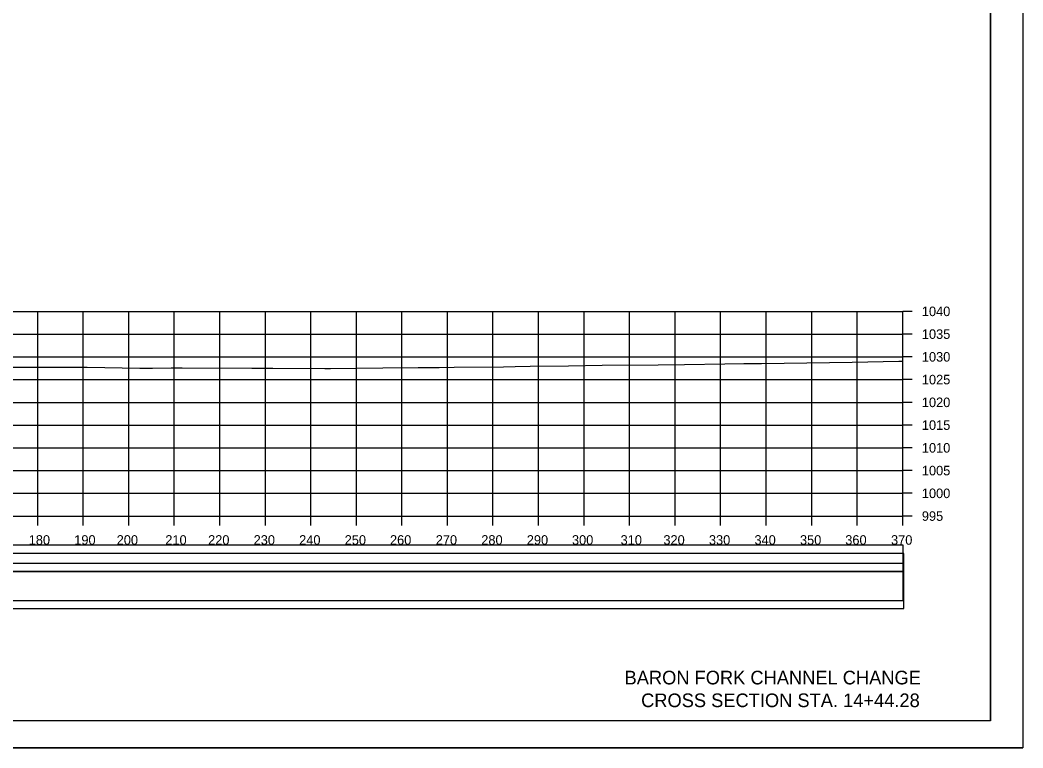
# Model space of a CAD drawing. Extents: x 1370565 to 1374448, y 301010 to 304637.
# Drawn here: x 1374227.6 to 1374447.9, y 302693 to 302853 of the extents above; entities that cross this region are included whole.
import ezdxf

# ---------------------------------------------------------------- set-up
doc = ezdxf.new("R2010")
doc.units = 0
for name, color, linetype in [('Default', 7, 'Continuous'), ('R_Axis', 7, 'Continuous'), ('R_Axis Annot', 7, 'Continuous'), ('R_Border', 7, 'Continuous'), ('R_Draft', 7, 'Continuous'), ('R_Drive', 7, 'Continuous'), ('R_Exist Surface', 7, 'Continuous'), ('R_Grid', 7, 'Continuous'), ('R_No Plot', 7, 'Continuous')]:
    doc.layers.add(name, color=color, linetype=linetype)

msp = doc.modelspace()

# ---------------------------------------------------------------- linework, layer by layer
at = {"layer": 'Default'}
for points in [[(1373981.44, 302733.61), (1374421.61, 302733.61), (1374421.61, 302737.6), (1373981.44, 302737.6)], [(1373981.44, 302725.39), (1374421.61, 302725.39), (1374421.61, 302733.53), (1373981.44, 302733.53)]]:
    msp.add_lwpolyline(points, close=True, dxfattribs=at)
at = {"layer": 'R_Axis'}
for p, q in [((1374421.52, 302743.98), (1374421.52, 302788.98)), ((1374423.62, 302788.98), (1374421.52, 302788.98)), ((1374423.62, 302783.98), (1374421.52, 302783.98)), ((1374423.62, 302778.98), (1374421.52, 302778.98)), ((1374423.62, 302773.98), (1374421.52, 302773.98)), ((1374423.62, 302768.98), (1374421.52, 302768.98)), ((1374423.62, 302763.98), (1374421.52, 302763.98)), ((1374423.62, 302758.98), (1374421.52, 302758.98)), ((1374423.62, 302753.98), (1374421.52, 302753.98)), ((1374423.62, 302748.98), (1374421.52, 302748.98)), ((1373981.52, 302743.98), (1374421.52, 302743.98)), ((1374231.52, 302741.88), (1374231.52, 302743.98)), ((1374241.52, 302741.88), (1374241.52, 302743.98)), ((1374251.52, 302741.88), (1374251.52, 302743.98)), ((1374261.52, 302741.88), (1374261.52, 302743.98)), ((1374271.52, 302741.88), (1374271.52, 302743.98)), ((1374281.52, 302741.88), (1374281.52, 302743.98)), ((1374291.52, 302741.88), (1374291.52, 302743.98)), ((1374301.52, 302741.88), (1374301.52, 302743.98)), ((1374311.52, 302741.88), (1374311.52, 302743.98)), ((1374321.52, 302741.88), (1374321.52, 302743.98)), ((1374331.52, 302741.88), (1374331.52, 302743.98)), ((1374341.52, 302741.88), (1374341.52, 302743.98)), ((1374351.52, 302741.88), (1374351.52, 302743.98)), ((1374361.52, 302741.88), (1374361.52, 302743.98)), ((1374371.52, 302741.88), (1374371.52, 302743.98)), ((1374381.52, 302741.88), (1374381.52, 302743.98)), ((1374391.52, 302741.88), (1374391.52, 302743.98)), ((1374401.52, 302741.88), (1374401.52, 302743.98)), ((1374411.52, 302741.88), (1374411.52, 302743.98)), ((1374421.52, 302741.88), (1374421.52, 302743.98)), ((1374423.62, 302743.98), (1374421.52, 302743.98))]:
    msp.add_line(p, q, dxfattribs=at)
at = {"layer": 'R_Border'}
for q in [(1374440.79, 303007.17), (1373966.52, 302698.98)]:
    msp.add_line((1374440.79, 302698.98), q, dxfattribs=at)
at = {"layer": 'R_Drive'}
for points in [[(1373981.52, 302731.78), (1374421.73, 302731.78), (1374421.73, 302735.77), (1373981.52, 302735.77)], [(1373981.52, 302723.63), (1374421.73, 302723.63), (1374421.73, 302731.78), (1373981.52, 302731.78)]]:
    msp.add_lwpolyline(points, close=True, dxfattribs=at)
at = {"layer": 'R_Exist Surface'}
msp.add_lwpolyline([(1374208.97, 302776.69), (1374228.36, 302776.72), (1374235.05, 302776.72), (1374240.22, 302776.73), (1374242.37, 302776.7), (1374253.96, 302776.48), (1374256.73, 302776.5), (1374260.83, 302776.54), (1374263.25, 302776.54), (1374278.55, 302776.51), (1374283.17, 302776.48), (1374294.56, 302776.44), (1374295.8, 302776.44), (1374307.33, 302776.56), (1374315.12, 302776.66), (1374319.69, 302776.67), (1374323.03, 302776.69), (1374333.81, 302776.81), (1374336.37, 302776.87), (1374339.69, 302776.93), (1374348.09, 302777.03), (1374355.52, 302777.12), (1374367.82, 302777.22), (1374373.59, 302777.31), (1374382.47, 302777.47), (1374386.59, 302777.52), (1374389.23, 302777.5), (1374390.48, 302777.52), (1374410.44, 302777.8), (1374420.63, 302778), (1374421.52, 302778.02)], dxfattribs=at)
at = {"layer": 'R_Grid'}
for p, q in [((1373981.52, 302788.98), (1374421.52, 302788.98)), ((1374231.52, 302743.98), (1374231.52, 302788.98)), ((1374241.52, 302743.98), (1374241.52, 302788.98)), ((1374251.52, 302743.98), (1374251.52, 302788.98)), ((1374261.52, 302743.98), (1374261.52, 302788.98)), ((1374271.52, 302743.98), (1374271.52, 302788.98)), ((1374281.52, 302743.98), (1374281.52, 302788.98)), ((1374291.52, 302743.98), (1374291.52, 302788.98)), ((1374301.52, 302743.98), (1374301.52, 302788.98)), ((1374311.52, 302743.98), (1374311.52, 302788.98)), ((1374321.52, 302743.98), (1374321.52, 302788.98)), ((1374331.52, 302743.98), (1374331.52, 302788.98)), ((1374341.52, 302743.98), (1374341.52, 302788.98)), ((1374351.52, 302743.98), (1374351.52, 302788.98)), ((1374361.52, 302743.98), (1374361.52, 302788.98)), ((1374371.52, 302743.98), (1374371.52, 302788.98)), ((1374381.52, 302743.98), (1374381.52, 302788.98)), ((1374391.52, 302743.98), (1374391.52, 302788.98)), ((1374401.52, 302743.98), (1374401.52, 302788.98)), ((1374411.52, 302743.98), (1374411.52, 302788.98)), ((1374421.52, 302743.98), (1374421.52, 302788.98)), ((1373981.52, 302783.98), (1374421.52, 302783.98)), ((1373981.52, 302778.98), (1374421.52, 302778.98)), ((1373981.52, 302773.98), (1374421.52, 302773.98)), ((1373981.52, 302768.98), (1374421.52, 302768.98)), ((1373981.52, 302763.98), (1374421.52, 302763.98)), ((1373981.52, 302758.98), (1374421.52, 302758.98)), ((1373981.52, 302753.98), (1374421.52, 302753.98)), ((1373981.52, 302748.98), (1374421.52, 302748.98)), ((1373981.52, 302743.98), (1374421.52, 302743.98))]:
    msp.add_line(p, q, dxfattribs=at)
at = {"layer": 'R_No Plot'}
msp.add_line((1373947.92, 302693.02), (1374447.92, 302693.02), dxfattribs=at)
for points in [[(1373947.91, 303013.02), (1374447.92, 303013.02), (1374447.92, 302693.01), (1373947.91, 302693.01)], [(1374317.4, 303007.17), (1374346.83, 303007.17), (1374346.83, 302992.35), (1374371, 302992.35), (1374405.8, 302992.35), (1374405.98, 302950.12), (1374440.79, 302950.12), (1374440.79, 302698.98), (1373966.52, 302698.98), (1373966.52, 303007.17)]]:
    msp.add_lwpolyline(points, close=True, dxfattribs=at)

# ---------------------------------------------------------------- texts
at = {"layer": 'R_Axis Annot'}
for s, p in [('1040', (1374425.72, 302787.93)), ('1035', (1374425.72, 302782.93)), ('1030', (1374425.72, 302777.93)), ('1025', (1374425.72, 302772.93)), ('1020', (1374425.72, 302767.93)), ('1015', (1374425.72, 302762.93)), ('1010', (1374425.72, 302757.93)), ('1005', (1374425.72, 302752.93)), ('1000', (1374425.72, 302747.93)), ('995', (1374425.72, 302742.93)), ('180', (1374229.55, 302737.68)), ('190', (1374239.55, 302737.68)), ('200', (1374248.87, 302737.68)), ('210', (1374259.55, 302737.68)), ('220', (1374268.95, 302737.68)), ('230', (1374278.95, 302737.68)), ('240', (1374288.95, 302737.68)), ('250', (1374298.95, 302737.68)), ('260', (1374308.9, 302737.68)), ('270', (1374318.95, 302737.68)), ('280', (1374328.95, 302737.68)), ('290', (1374338.95, 302737.68)), ('300', (1374348.87, 302737.68)), ('310', (1374359.55, 302737.68)), ('320', (1374368.95, 302737.68)), ('330', (1374378.95, 302737.68)), ('340', (1374388.95, 302737.68)), ('350', (1374398.95, 302737.68)), ('360', (1374408.9, 302737.68)), ('370', (1374418.95, 302737.68))]:
    msp.add_text(s, height=2.1, dxfattribs=at).set_placement(p)
at = {"layer": 'R_Draft'}
for s, p in [(' BARON FORK CHANNEL CHANGE', (1374359.31, 302706.98)), ('CROSS SECTION STA. 14+44.28', (1374364.06, 302701.98))]:
    msp.add_text(s, height=3, dxfattribs=at).set_placement(p)

doc.saveas('drawing.dxf')
